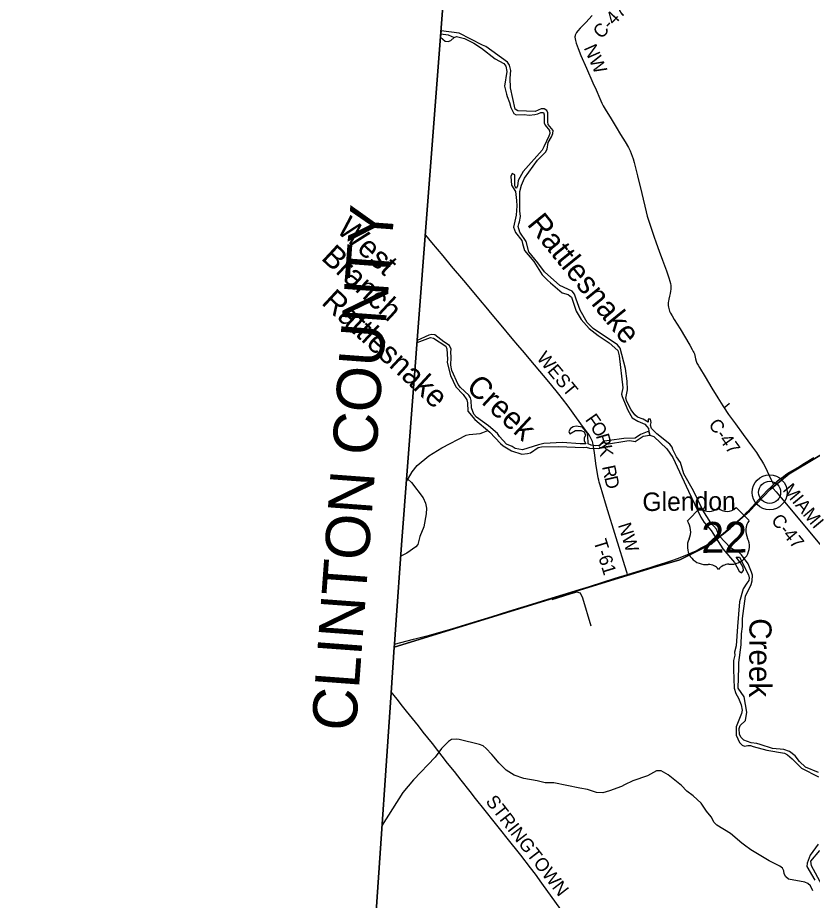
# Model space of a CAD drawing. Extents: x -51392 to 1635000, y 156707 to 696232.
# Drawn here: x 90391 to 108334, y 467382 to 487309 of the extents above; entities that cross this region are included whole.
import ezdxf

# ---------------------------------------------------------------- set-up
doc = ezdxf.new("R2010")
doc.units = 0
for name, color, linetype in [('GM_X_Adjacent_County', 7, 'Continuous'), ('GM_X_Adjacent_County_Text', 7, 'Continuous'), ('GM_X_County', 7, 'Continuous'), ('GM_X_County_Road', 7, 'Continuous'), ('GM_X_County_Road_Text', 7, 'Continuous'), ('GM_X_Major_River', 7, 'Continuous'), ('GM_X_Major_River_Text', 7, 'Continuous'), ('GM_X_Minor_River', 7, 'Continuous'), ('GM_X_Minor_River_Text', 7, 'Continuous'), ('GM_X_Township', 7, 'Continuous'), ('GM_X_Township_Road', 7, 'Continuous'), ('GM_X_Township_Road_Text', 7, 'Continuous'), ('GM_X_Unincorporated', 7, 'Continuous'), ('GM_X_Unincorporated_Text', 7, 'Continuous'), ('GM_X_US_Route', 7, 'Continuous'), ('GM_X_US_Shield', 7, 'Continuous')]:
    doc.layers.add(name, color=color, linetype=linetype)

msp = doc.modelspace()

# ---------------------------------------------------------------- linework, layer by layer
at = {"layer": 'GM_X_Adjacent_County'}
msp.add_lwpolyline([(58642, 493232), (60591, 493072), (62303, 492928), (66254, 492596), (68108, 492440), (73745, 491967), (74329, 491918), (76813, 491706), (86490, 490884), (87254, 490819), (90493, 490546), (92603, 490367), (94718, 490188), (100159, 489728), (99590, 482380), (99055, 475410), (98926, 473605), (98897, 473168), (98892, 473100), (98821, 472065), (98149, 462191)], dxfattribs=at)
at = {"layer": 'GM_X_County'}
msp.add_lwpolyline([(98149, 462191), (98821, 472065), (98892, 473100), (98897, 473168), (98926, 473605), (99055, 475410), (99590, 482380), (100159, 489728), (94718, 490188), (92603, 490367), (90493, 490546), (87254, 490819), (86490, 490884), (76813, 491706), (74329, 491918), (73745, 491967), (74013, 495268), (74241, 498091), (74563, 502065), (74862, 505867)], dxfattribs=at)
at = {"layer": 'GM_X_County_Road'}
for points in [[(103364, 487358), (103219, 487202), (103095, 487071), (103039, 487011), (103008, 486972), (102998, 486958), (102990, 486944), (102983, 486928), (102978, 486912), (102975, 486896), (102973, 486879), (102973, 486862), (102975, 486845), (102977, 486829), (102984, 486796), (103002, 486733), (103023, 486670), (103046, 486609), (103110, 486458), (103235, 486172), (103380, 485841), (103452, 485676), (103537, 485480), (103584, 485375), (103614, 485317), (103655, 485245), (103792, 485022), (103903, 484839), (104003, 484670), (104105, 484502), (104180, 484374), (104218, 484302), (104246, 484243), (104269, 484182), (104290, 484120), (104311, 484041), (104385, 483738), (104481, 483339), (104581, 482925), (104606, 482829), (104634, 482735), (104685, 482579), (104755, 482377), (104810, 482223), (104875, 482037), (104947, 481836), (105037, 481590), (105093, 481435), (105118, 481357), (105129, 481310), (105137, 481262), (105139, 481213), (105137, 481181), (105132, 481132), (105123, 481084), (105107, 481021), (105091, 480957), (105082, 480908), (105079, 480875), (105079, 480842), (105081, 480809), (105085, 480776), (105092, 480743), (105101, 480712), (105112, 480680), (105133, 480635), (105165, 480578), (105216, 480493), (105346, 480284), (105565, 479918), (105623, 479819), (105646, 479776), (105659, 479747), (105670, 479716), (105679, 479685), (105695, 479604), (105710, 479557), (105729, 479511), (105752, 479467), (105785, 479410), (105913, 479200), (106067, 478948), (106203, 478724), (106315, 478542), (106341, 478502)], [(106341, 478502), (106369, 478459), (106397, 478419)], [(106397, 478419), (106444, 478352), (106598, 478139), (106772, 477901), (106879, 477755), (106985, 477609), (107071, 477489), (107144, 477380), (107187, 477311), (107228, 477240), (107273, 477153), (107351, 476990), (107415, 476857), (107437, 476813), (107457, 476772)], [(107412, 476728), (107441, 476692), (107452, 476680), (107516, 476605), (107632, 476467), (107863, 476190), (108083, 475925), (108198, 475785), (108606, 475293)]]:
    msp.add_lwpolyline(points, dxfattribs=at)
at = {"layer": 'GM_X_Major_River'}
for p, q in [((99951, 487009), (99941, 486869)), ((104642, 477971), (104662, 477882))]:
    msp.add_line(p, q, dxfattribs=at)
for points in [[(106754, 473564), (106755, 473746), (106821, 474246), (106955, 474510), (106978, 474592), (106979, 474724), (106961, 474791), (106884, 474978), (106737, 475179), (106679, 475234), (106487, 475343), (106239, 475605), (106199, 475683), (106172, 475761), (106039, 475908), (105861, 476192), (105649, 476628), (105433, 477013), (105358, 477264), (105263, 477391), (105186, 477562), (105166, 477612), (105114, 477681), (104819, 477911), (104705, 478032), (104677, 478107), (104694, 478171), (104676, 478243), (104626, 478245), (104626, 478175), (104512, 478248), (104386, 478289), (104324, 478346), (104246, 478453), (104147, 478646), (104126, 478722), (104159, 478908), (104150, 479101), (104112, 479392), (103997, 479848), (103935, 479922), (103791, 480021), (103705, 480076), (103384, 480295), (103248, 480424), (103093, 480706), (103003, 480953), (102965, 481070), (102908, 481138), (102630, 481265), (102284, 481574), (102137, 481775), (101936, 482023), (101872, 482252), (101726, 482468), (101693, 482595), (101706, 482651), (101718, 482703), (101743, 482817), (101728, 482951), (101727, 483388), (101764, 483530), (101833, 483684), (102125, 484089), (102311, 484270), (102347, 484338), (102372, 484490), (102444, 484622), (102472, 484692), (102479, 484762), (102371, 484899), (102360, 484959), (102365, 485163), (102339, 485214), (102279, 485248), (102213, 485253), (102074, 485192), (101883, 485197), (101685, 485207), (101623, 485241), (101518, 485723), (101509, 485939), (101524, 486116), (101497, 486234), (101453, 486301), (100958, 486655), (100886, 486688), (100362, 486960), (99951, 487009)], [(99941, 486869), (100044, 486776), (100114, 486772), (100170, 486795), (100243, 486859), (100299, 486882), (100480, 486837), (100690, 486735), (100867, 486622), (101173, 486379), (101367, 486273), (101415, 486215), (101432, 486090), (101384, 485764), (101428, 485583), (101444, 485529), (101499, 485394), (101527, 485280), (101594, 485145), (101648, 485115), (101825, 485121), (101937, 485104), (102064, 485120), (102136, 485141), (102202, 485167), (102267, 485170), (102282, 485118), (102277, 484934), (102299, 484879), (102398, 484764), (102408, 484696), (102385, 484630), (102269, 484392), (102237, 484316), (101808, 483835)], [(101808, 483835), (101690, 483635), (101673, 483505), (101645, 483453), (101617, 483513), (101613, 483760), (101557, 483790), (101524, 483726), (101539, 483528), (101632, 483381), (101647, 483248), (101651, 483184), (101662, 483062), (101645, 482849), (101585, 482577), (101628, 482459), (101771, 482275), (101791, 482209), (101832, 482050), (102043, 481806), (102230, 481504), (102357, 481379), (102423, 481322), (102685, 481098), (102819, 481057), (102893, 480996), (103003, 480683), (103112, 480491), (103295, 480294), (103497, 480132), (103745, 479968), (103944, 479796), (103974, 479677), (104057, 478955), (104028, 478807), (104042, 478755), (104067, 478684), (104168, 478449), (104267, 478274), (104391, 478197), (104554, 478135), (104600, 478080), (104636, 478035), (104642, 477971)], [(104662, 477882), (104756, 477854), (105045, 477573), (105182, 477377), (105539, 476621), (105818, 476034), (105891, 475909), (106050, 475731), (106086, 475669), (106312, 475316), (106573, 475012), (106682, 474815), (106736, 474776), (106781, 474830), (106775, 474894), (106714, 475003), (106616, 475128), (106685, 475131), (106891, 474731), (106906, 474663), (106900, 474603), (106857, 474539), (106774, 474411), (106690, 474119), (106647, 473563)], [(106647, 473563), (106611, 473125), (106575, 472985), (106581, 472920), (106553, 472796), (106557, 472594), (106570, 472173), (106604, 472049), (106666, 471943), (106726, 471793), (106747, 471674), (106737, 471602), (106611, 471298), (106617, 471114), (106686, 470943), (106750, 470885), (106804, 470863), (106874, 470881), (106940, 470877), (107001, 470857), (107307, 470775), (107703, 470702), (107773, 470670), (107879, 470580), (108085, 470363), (108475, 470173)], [(108469, 470269), (108179, 470387), (108045, 470520), (107945, 470648), (107821, 470746), (107689, 470784), (107435, 470809), (107155, 470899), (107083, 470923), (106955, 470939), (106785, 470999), (106723, 471056), (106689, 471124), (106679, 471258), (106707, 471328), (106821, 471446), (106854, 471634), (106792, 471977), (106662, 472173), (106675, 472640), (106673, 472754), (106728, 473151), (106734, 473401), (106754, 473564)], [(108462, 468647), (108284, 468400), (108214, 468224), (108212, 468148), (108387, 467837)], [(108545, 467729), (108316, 468164), (108296, 468264), (108502, 468506)]]:
    msp.add_lwpolyline(points, dxfattribs=at)
at = {"layer": 'GM_X_Minor_River'}
for p, q in [((99412, 480023), (99408, 479972)), ((104662, 477882), (104642, 477971))]:
    msp.add_line(p, q, dxfattribs=at)
for points in [[(99947, 486942), (100109, 486924), (100243, 486859)], [(99408, 479972), (99715, 480087), (99781, 480075), (100057, 479890), (100083, 479834), (100093, 479597), (100087, 479525), (100161, 479228), (100286, 478971), (100453, 478799), (100535, 478680), (100548, 478610), (100557, 478429), (100714, 478238), (101050, 477953), (101293, 477696), (101355, 477642), (101544, 477528), (101777, 477454), (101901, 477466), (101968, 477487), (102145, 477606), (102219, 477620), (102609, 477627), (103161, 477605), (103229, 477612), (103303, 477588), (103508, 477586), (103564, 477598), (103689, 477681), (104145, 477754), (104216, 477763), (104334, 477744), (104513, 477861), (104662, 477882)], [(104642, 477971), (104453, 477902), (104336, 477819), (104075, 477812), (103752, 477761), (103692, 477753), (103635, 477745), (103589, 477694), (103520, 477654), (103444, 477641), (103340, 477655), (103272, 477690), (103267, 477887), (103251, 477939), (103142, 478062), (103003, 478083), (102937, 478073), (102875, 478034), (102836, 477970), (102860, 477910), (102989, 477987), (103115, 477990), (103183, 477957), (103209, 477883), (103180, 477817), (103180, 477755), (103221, 477686), (103169, 477689), (103095, 477691), (102696, 477716), (102270, 477699), (102152, 477664), (101789, 477551), (101623, 477582), (101559, 477626), (101425, 477677), (101268, 477851), (101224, 477919), (101022, 478097), (100749, 478292), (100689, 478356), (100636, 478497), (100631, 478663), (100615, 478724), (100580, 478790), (100386, 478956), (100338, 479026), (100190, 479340), (100171, 479465), (100178, 479647), (100169, 479755), (100181, 479823), (100140, 479910), (100010, 479989), (99808, 480145), (99742, 480155), (99675, 480142), (99412, 480023)], [(99166, 476819), (99295, 477054), (99411, 477199), (99671, 477418), (99969, 477594), (100515, 477881), (100586, 477902), (100837, 477918), (100893, 477942), (101005, 477991)], [(99204, 476887), (99282, 476815), (99544, 476471), (99598, 476350), (99623, 476233), (99614, 476105), (99560, 475815), (99472, 475593), (99425, 475417), (99378, 475359), (99178, 475220), (99040, 475153)], [(103337, 473572), (103152, 474205), (103096, 474318), (103018, 474340), (102857, 474293), (102455, 474164)], [(108341, 467597), (108289, 467713), (108235, 467763), (108167, 467790), (107797, 467860), (107737, 467912), (107697, 467978), (107691, 468046), (107661, 468110), (107603, 468157), (107359, 468271), (106945, 468520), (106799, 468630), (106743, 468670), (106485, 468893), (106177, 469083), (106119, 469139), (106048, 469270), (105946, 469396), (105822, 469576), (105646, 469745), (105498, 469849), (105382, 469973), (105078, 470214), (104922, 470306), (104812, 470306), (104610, 470192), (104283, 470082), (104095, 469990), (104027, 469956), (103753, 469852), (103606, 469808), (103458, 469816), (103258, 469883), (103082, 469915), (102496, 470034), (102304, 470034), (102120, 470078), (101818, 470136), (101598, 470207), (101420, 470319), (101254, 470483), (101148, 470614), (101100, 470674), (100970, 470812), (100900, 470868), (100820, 470900), (100362, 471011), (100304, 471021), (100186, 471011), (100117, 470969), (99961, 470809), (99817, 470615), (99328, 470102), (99091, 469816), (98621, 469080)]]:
    msp.add_lwpolyline(points, dxfattribs=at)
at = {"layer": 'GM_X_Township'}
for points in [[(110165, 478417), (107808, 477008), (107384, 476659), (106915, 476171), (106859, 476122), (106113, 475475), (106063, 475431), (105342, 475069), (105263, 475046), (104817, 474915), (104151, 474718), (98892, 473100), (98897, 473168), (98926, 473605), (99055, 475410), (99590, 482380), (100159, 489728), (94718, 490188), (92603, 490367), (90493, 490546), (87254, 490819)], [(108742, 447621), (105839, 446363), (100106, 443877), (97020, 442539), (96805, 442445), (96826, 442764), (97097, 446742), (97917, 458796), (98094, 461383), (98149, 462191), (98821, 472065), (98892, 473100), (104151, 474718), (104817, 474915), (105263, 475046), (105342, 475069), (106063, 475431), (106113, 475475), (106859, 476122), (106915, 476171), (107384, 476659), (107808, 477008), (110165, 478417)]]:
    msp.add_lwpolyline(points, dxfattribs=at)
at = {"layer": 'GM_X_Township_Road'}
for points in [[(104160, 474740), (104151, 474767), (104136, 474814), (103903, 475566), (103687, 476272), (103588, 476602), (103564, 476680), (103535, 476774), (103521, 476821), (103509, 476869), (103500, 476917), (103448, 477241), (103429, 477371), (103413, 477485), (103399, 477582), (103386, 477663), (103376, 477711), (103367, 477743), (103356, 477774), (103343, 477804), (103319, 477847), (103293, 477888), (103237, 477969), (103110, 478140), (102974, 478325), (102818, 478537), (102690, 478707), (102609, 478810), (102422, 479039), (102264, 479228), (101978, 479566), (101831, 479742), (101683, 479918), (101557, 480069), (101304, 480370), (101104, 480609), (100966, 480772), (100839, 480923), (100734, 481049), (100461, 481376), (100186, 481702), (99996, 481929), (99744, 482231), (99604, 482398)], [(106341, 478502), (106368, 478525), (106454, 478600), (106466, 478611)], [(102717, 467093), (102359, 467584), (102225, 467770), (102081, 467970), (101973, 468114), (101751, 468399), (101445, 468784), (101302, 468964), (101149, 469157), (100945, 469414), (100731, 469685), (100609, 469839), (100405, 470096), (100251, 470288), (100099, 470482), (99754, 470920), (99550, 471177), (99438, 471319), (99305, 471486), (99172, 471652), (99081, 471769), (98959, 471923), (98826, 472090)]]:
    msp.add_lwpolyline(points, dxfattribs=at)
at = {"layer": 'GM_X_Unincorporated'}
for radius in [393, 249]:
    msp.add_circle((107369, 476593), radius, dxfattribs=at)
at = {"layer": 'GM_X_US_Route'}
for points in [[(106849, 476135), (106890, 476178), (107125, 476430), (107317, 476632), (107409, 476725), (107412, 476728), (107457, 476772), (107479, 476793), (107528, 476837), (107592, 476888), (107671, 476946), (107738, 476993), (107821, 477046), (108003, 477157), (108157, 477251), (108368, 477378)], [(104810, 474942), (105022, 475007), (105163, 475052), (105287, 475096), (105425, 475149), (105516, 475186), (105621, 475233), (105709, 475276), (105826, 475337), (105926, 475393), (106025, 475452), (106135, 475523), (106230, 475588), (106324, 475655), (106402, 475715), (106478, 475778), (106564, 475854), (106659, 475944), (106776, 476059), (106849, 476135)], [(98900, 473162), (99326, 473275), (99691, 473370), (100039, 473466), (100213, 473516), (100605, 473636), (101106, 473792), (101482, 473908), (101748, 473991), (101999, 474068), (102360, 474179), (102704, 474287), (103002, 474379), (103299, 474471), (103878, 474652), (104160, 474740), (104693, 474906), (104810, 474942)]]:
    msp.add_lwpolyline(points, dxfattribs=at)
at = {"layer": 'GM_X_US_Shield'}
for p, q in [((106903, 475961), (106611, 476248)), ((105799, 476241), (105511, 475948)), ((105927, 474965), (105985, 474966)), ((106449, 474970), (106507, 474971))]:
    msp.add_line(p, q, dxfattribs=at)
for centre, radius, start, end in [((106000, 476450), 290, 226.1115, 314.9656), ((106406, 476453), 290, 226.1115, 314.9656), ((105181, 475712), 406, 335.0857, 35.5395), ((107238, 475731), 406, 145.5376, 205.9914), ((105918, 475371), 406, 155.3705, 271.1768), ((106507, 475377), 406, 269.9003, 25.7066), ((105987, 474676), 290, 37.4084, 90.5385), ((106451, 474680), 290, 90.5385, 143.6686)]:
    msp.add_arc(centre, radius, start, end, dxfattribs=at)

# ---------------------------------------------------------------- texts
at = {"layer": 'GM_X_Adjacent_County_Text'}
msp.add_text('CLINTON COUNTY', height=1000, rotation=85.7634, dxfattribs=at).set_placement((98024, 471182))
at = {"layer": 'GM_X_County_Road_Text'}
for s, rotation, p in [('C-47', 47.4461, (103571, 486813)), ('NW', 293.6263, (103167, 486627)), ('C-47', 305.8387, (105974, 478122)), ('MIAMI', 309.737, (107648, 476639)), ('C-47', 309.7322, (107386, 475954))]:
    msp.add_text(s, height=300, rotation=rotation, dxfattribs=at).set_placement(p)
at = {"layer": 'GM_X_Major_River_Text'}
for s, height, rotation, p in [('Rattlesnake', 499.97, 308.9971, (101876, 482641)), ('Creek', 500, 269.748, (106914, 473752))]:
    msp.add_text(s, height=height, rotation=rotation, dxfattribs=at).set_placement(p)
at = {"layer": 'GM_X_Minor_River_Text'}
for s, height, rotation, p in [('West', 500, 317.1667, (97565, 482495)), ('Branch', 500, 317.1667, (97224, 481862)), ('Rattlesnake', 499.96, 317.1667, (97229, 480856)), ('Creek', 500, 317.1671, (100493, 478936))]:
    msp.add_text(s, height=height, rotation=rotation, dxfattribs=at).set_placement(p)
at = {"layer": 'GM_X_Township_Road_Text'}
for s, rotation, p in [('WEST', 309.6689, (102093, 479619)), ('F', 305.2632, (103193, 478233)), ('O', 303.2668, (103308, 478070)), ('R', 285.9854, (103443, 477871)), ('K', 278.6048, (103509, 477644)), ('R', 281.6694, (103583, 477174)), ('D', 282.9727, (103635, 476926)), ('NW', 287.2777, (103941, 475856)), ('T-61', 287.0687, (103389, 475488)), ('STRINGTOWN', 307.7172, (100943, 469614))]:
    msp.add_text(s, height=300, rotation=rotation, dxfattribs=at).set_placement(p)
at = {"layer": 'GM_X_Unincorporated_Text'}
msp.add_text('Glendon', height=417, rotation=0.5386, dxfattribs=at).set_placement((104498, 476170))
at = {"layer": 'GM_X_US_Shield'}
msp.add_text('22', height=696.1, rotation=0.5385, dxfattribs=at).set_placement((105829, 475226))

doc.saveas('drawing.dxf')
